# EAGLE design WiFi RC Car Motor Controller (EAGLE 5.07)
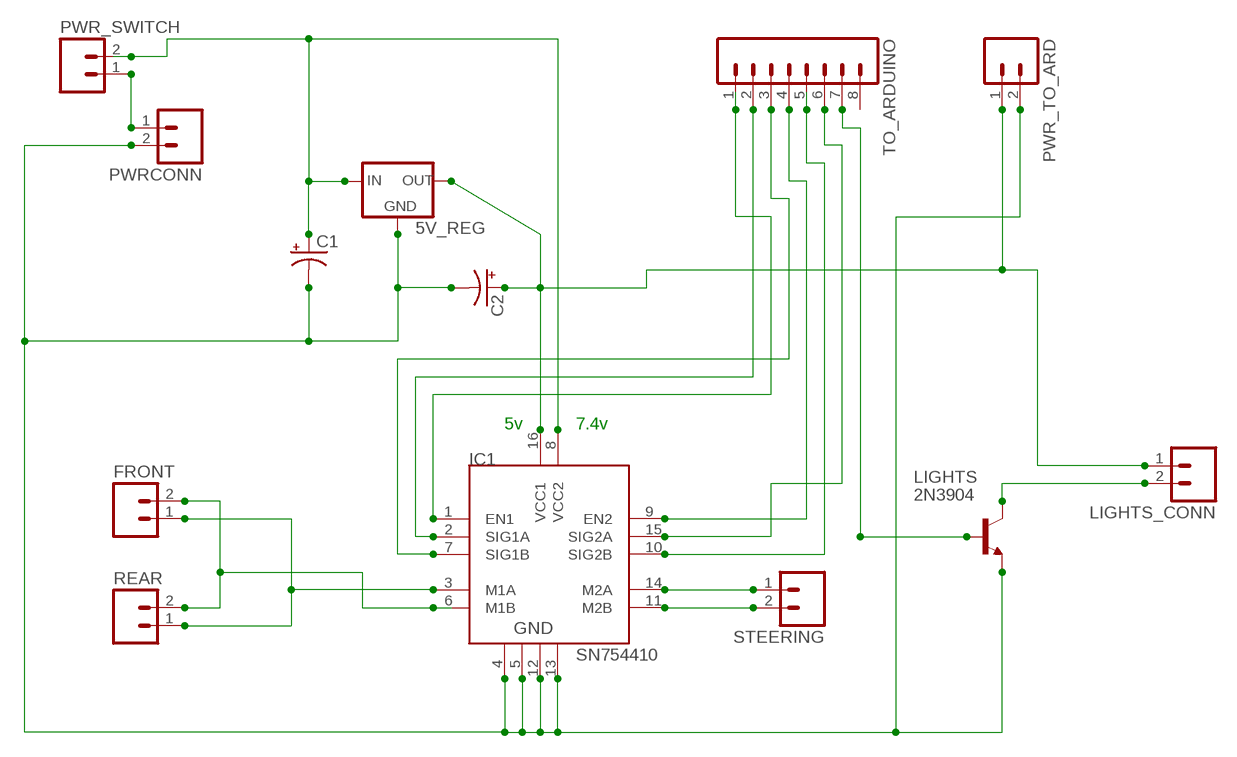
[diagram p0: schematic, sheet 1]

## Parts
5V_REG  V_REG_78XXSIDE  [78XXL]
C1  CAP_POLPTH2  [CPOL-RADIAL-10UF-25V]
C2  CAP_POLPTH2  [CPOL-RADIAL-10UF-25V]
FRONT  M023.5MM  [SCREWTERMINAL-3.5MM-2]
IC1  SN754410  [DIP16]
LIGHTS  2N3904  [TO92]
LIGHTS_CONN  M023.5MM  [SCREWTERMINAL-3.5MM-2]
PWR_SWITCH  M023.5MM  [SCREWTERMINAL-3.5MM-2]
PWR_TO_ARD  M023.5MM  [SCREWTERMINAL-3.5MM-2]
PWRCONN  M023.5MM  [SCREWTERMINAL-3.5MM-2]
REAR  M023.5MM  [SCREWTERMINAL-3.5MM-2]
STEERING  M023.5MM  [SCREWTERMINAL-3.5MM-2]
TO_ARDUINO  M08LONGPADS  [1X08_LONGPADS]

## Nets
N$1: FRONT.1 IC1.3(M1A) REAR.1
N$2: 5V_REG.GND C1.2(-) C2.2(-) IC1.4 IC1.5 IC1.12 IC1.13 LIGHTS.3(E) PWR_TO_ARD.2 PWRCONN.2
N$3: FRONT.2 IC1.6(M1B) REAR.2
N$4: IC1.14(M2A) STEERING.1
N$5: IC1.11(M2B) STEERING.2
N$6: PWR_SWITCH.1 PWRCONN.1
N$7: 5V_REG.IN C1.1(+) IC1.8(VCC2) PWR_SWITCH.2
N$8: 5V_REG.OUT C2.1(+) IC1.16(VCC1) LIGHTS_CONN.1 PWR_TO_ARD.1
N$9: IC1.1(EN1) TO_ARDUINO.1
N$10: IC1.2(SIG1A) TO_ARDUINO.2
N$11: IC1.7(SIG1B) TO_ARDUINO.3
N$12: LIGHTS.2(B) TO_ARDUINO.7
N$13: IC1.9(EN2) TO_ARDUINO.4
N$14: IC1.15(SIG2A) TO_ARDUINO.6
N$15: IC1.10(SIG2B) TO_ARDUINO.5
N$18: LIGHTS.1(C) LIGHTS_CONN.2
Unconnected: TO_ARDUINO.8

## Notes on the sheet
- 5v | 7.4v

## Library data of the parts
5V_REG = SparkFun:V_REG_78XX: Voltage Regulator Standard 7805 5V regulator. IGO (Input Ground Output). Spark Fun Electronics SKU : COM-00107
C1 C2 = SparkFun:CAP_POL: Capacitor Polarized
FRONT LIGHTS_CONN PWR_SWITCH PWR_TO_ARD PWRCONN REAR STEERING = SparkFun:M02: Header 2
IC1 = HBridge:SN754410: Quadruple half-H driver
LIGHTS = transistor:2N3904: NPN TRANSISTOR
TO_ARDUINO = SparkFun:M08: Header 8 Standard 8-pin 0.1" header. Use with straight break away headers (SKU : PRT-00116), right angle break away headers (PRT-00553), swiss pins (PRT-00743), machine pins (PRT-00117), and female headers (PRT-00115).

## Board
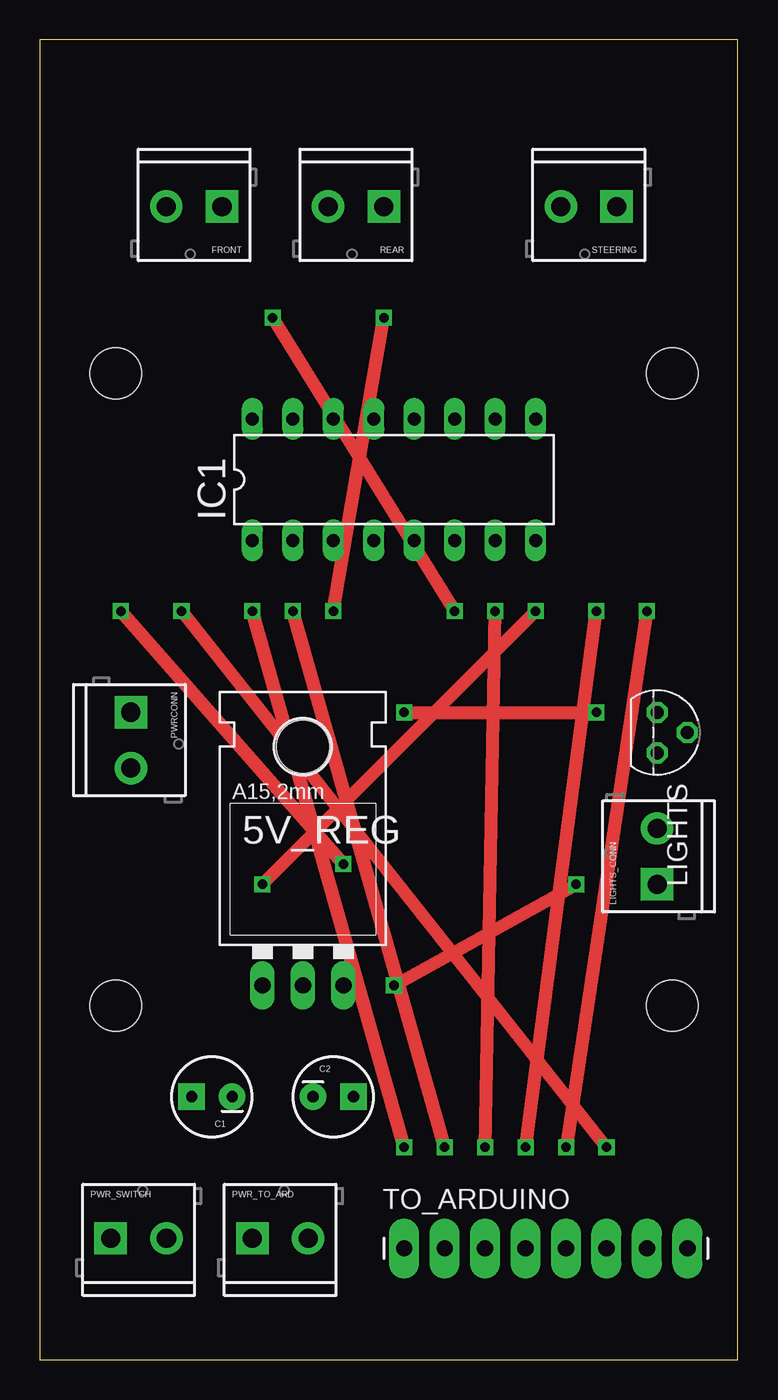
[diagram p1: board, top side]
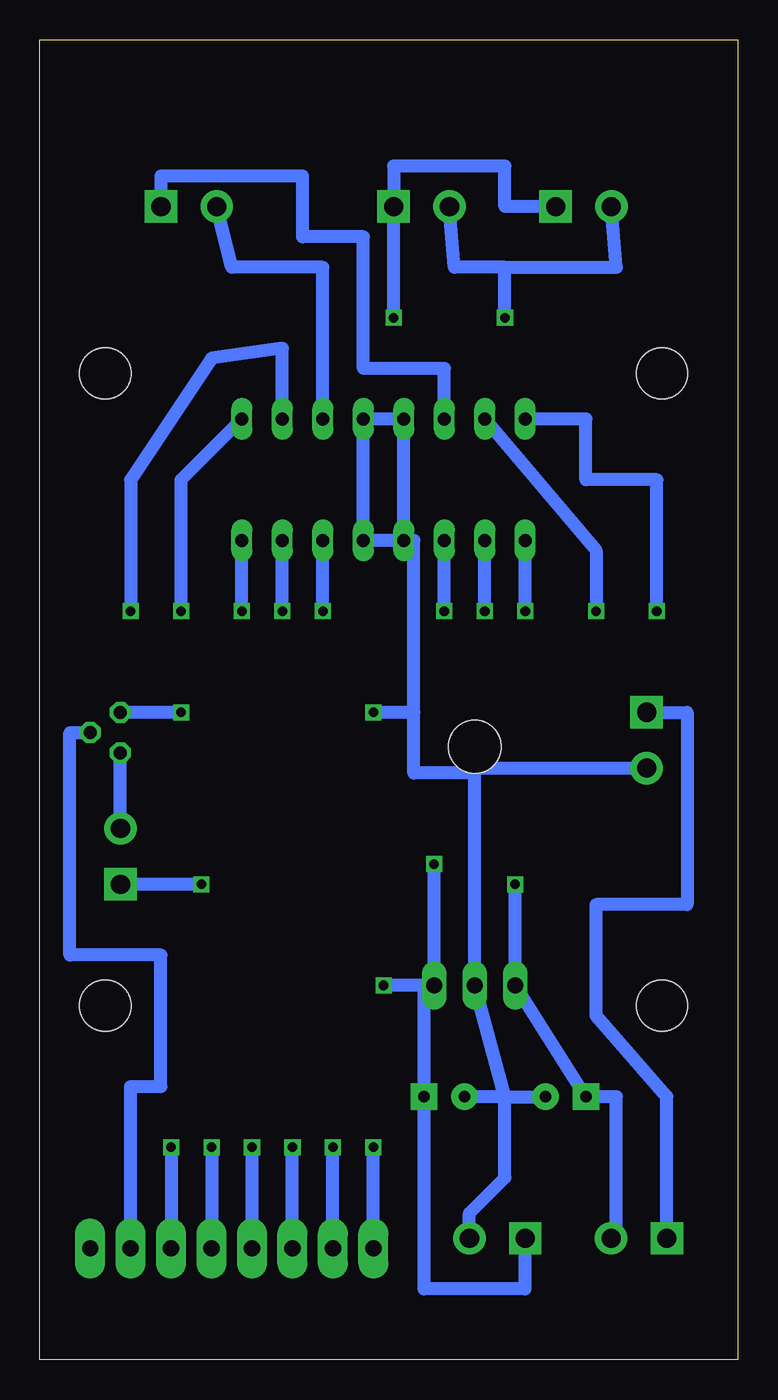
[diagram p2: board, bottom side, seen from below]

Size 43.8 x 82.86 mm. Coordinates in mm from the lower left corner, seen from the top.
Outline: 0,0 43.8,0 43.8,82.86 0,82.86 0,0
Copper layers (1*16): Top 0.035mm / dielectric 1.5mm / Bottom 0.035mm
Design rules "default": minimum track width 10mil, minimum drill 24mil, track to track 8mil, track to pad 8mil, pad to pad 8mil, via to via 8mil, smd to smd 8mil, copper to edge 40mil, drill to drill 8mil, minimum pad ring 10mil, minimum via ring 8mil, stop-mask expansion 4mil, vias tented up to drill 0mil, thermal gap 10mil
Holes 3.2 mm at 4.76,61.91 39.69,61.91 4.76,22.23 39.69,22.23

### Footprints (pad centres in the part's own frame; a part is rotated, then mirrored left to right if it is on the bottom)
78XXL = drill 1.016 long: GND 0,-3.81; IN -2.54,-3.81; OUT 2.54,-3.81 | hole 3.302: 0,11.176
CPOL-RADIAL-10UF-25V = drill 0.7 pad 1.651 square: 1 1.27,0 | drill 0.7 pad 1.651 round: 2 -1.27,0
SCREWTERMINAL-3.5MM-2 = drill 1.2 pad 2.032 square: 1 0,0 | drill 1.2 pad 2.032 round: 2 3.5,0
DIP16 = drill 0.813 long: 1 -10.16,-3.81; 2 -7.62,-3.81; 3 -5.08,-3.81; 4 -2.54,-3.81; 5 0,-3.81; 6 2.54,-3.81; 7 5.08,-3.81; 8 7.62,-3.81; 9 7.62,3.81; 10 5.08,3.81; 11 2.54,3.81; 12 0,3.81; 13 -2.54,3.81; 14 -5.08,3.81; 15 -7.62,3.81; 16 -10.16,3.81
TO92 = drill 0.813 octagon: 1 1.27,0; 2 0,1.905; 3 -1.27,0
1X08_LONGPADS = drill 1.016 pad 1.88 long: 1 0,0; 2 2.54,0; 3 5.08,0; 4 7.62,0; 5 10.16,0; 6 12.7,0; 7 15.24,0; 8 17.78,0

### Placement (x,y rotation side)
5V_REG  16.51,27.3 0 top
C1  10.79,16.51 180 top
C2  18.41,16.51 0 top
FRONT  11.43,72.39 180 top
IC1  23.5,55.24 0 top
LIGHTS  38.73,39.37 270 top
LIGHTS_CONN  38.73,29.84 90 top
PWR_SWITCH  4.45,7.62 0 top
PWR_TO_ARD  13.34,7.62 0 top
PWRCONN  5.71,40.64 270 top
REAR  21.59,72.39 180 top
STEERING  36.2,72.39 180 top
TO_ARDUINO  22.86,6.99 0 top

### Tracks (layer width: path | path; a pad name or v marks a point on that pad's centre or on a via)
N$1  (via drill 0.6)
  Top 0.813: v18.41,46.99 v21.59,65.41
  Bottom 0.813: v18.41,46.99 IC1.3 | v21.59,65.41 REAR.1 21.59,74.93 14.61,74.93 14.61,72.39 FRONT.1
N$2  (via drill 0.6)  (1 unrouted)
  Top 0.813: v22.86,40.64 34.92,40.64
  Bottom 0.813: 14.61,16.51 C1.2 | 14.61,16.51 14.61,11.43 16.84,9.2 PWR_TO_ARD.2 | 14.61,16.51 14.65,16.67 | 14.65,16.67 5V_REG.GND 16.51,36.83 | C2.2 14.65,16.51 14.65,16.67 | PWRCONN.2 16.51,37.14 16.51,36.83 | IC1.4 20.32,51.44 20.32,40.64 | 20.32,40.64 20.32,36.83 16.51,36.83 | IC1.4 IC1.5 IC1.12 IC1.13 IC1.4 | 34.92,40.64 LIGHTS.3 | 20.32,40.64 v22.86,40.64
N$3  (via drill 0.6)
  Top 0.813: v26.04,46.99 v14.61,65.41
  Bottom 0.813: FRONT.2 7.62,68.58 14.61,68.58 | 14.61,68.58 17.78,68.58 REAR.2 | v26.04,46.99 IC1.6 | v14.61,65.41 14.61,68.58
N$4
  Bottom 0.813: IC1.14 18.41,62.23 23.5,62.23 23.5,70.48 27.3,70.48 27.3,74.3 36.2,74.3 STEERING.1
N$5
  Bottom 0.813: IC1.11 26.04,68.58 31.75,68.58 STEERING.2
N$6
  Bottom 0.813: PWR_SWITCH.1 4.45,16.51 8.89,21.59 8.89,28.57 3.17,28.57 3.17,40.64 PWRCONN.1
N$7  (via drill 0.6)
  Top 0.813: v13.97,29.84 v31.11,46.99
  Bottom 0.813: PWR_SWITCH.2 7.62,7.62 7.62,16.51 C1.1 5V_REG.IN v13.97,29.84 | v31.11,46.99 IC1.8
N$8  (via drill 0.6)
  Top 0.813: v22.23,23.5 v33.66,29.84 | v19.05,31.11 v5.08,46.99
  Bottom 0.813: PWR_TO_ARD.1 13.34,4.45 19.68,4.45 C2.1 19.68,23.5 | 19.68,23.5 5V_REG.OUT v19.05,31.11 | v33.66,29.84 LIGHTS_CONN.1 | 19.68,23.5 v22.23,23.5 | v5.08,46.99 5.08,55.24 9.53,55.24 9.53,59.05 IC1.16
N$9  (via drill 0.6)
  Top 0.813: v22.86,13.34 v13.34,46.99
  Bottom 0.813: TO_ARDUINO.1 v22.86,13.34 | v13.34,46.99 IC1.1
N$10  (via drill 0.6)
  Top 0.813: v25.4,13.34 v15.88,46.99
  Bottom 0.813: TO_ARDUINO.2 v25.4,13.34 | v15.88,46.99 IC1.2
N$11  (via drill 0.6)
  Top 0.813: v27.94,13.34 v28.57,46.99
  Bottom 0.813: TO_ARDUINO.3 v27.94,13.34 | v28.57,46.99 IC1.7
N$12
  Bottom 0.813: TO_ARDUINO.7 38.1,17.14 36.2,17.14 36.2,25.4 41.91,25.4 41.91,39.37 LIGHTS.2
N$13  (via drill 0.6)
  Top 0.813: v30.48,13.34 v34.92,46.99
  Bottom 0.813: TO_ARDUINO.4 v30.48,13.34 | v34.92,46.99 34.92,55.24 IC1.9
N$14  (via drill 0.6)
  Top 0.813: v8.89,46.99 v35.56,13.34
  Bottom 0.813: IC1.15 8.89,50.8 v8.89,46.99 | v35.56,13.34 TO_ARDUINO.6 35.56,6.35
N$15  (via drill 0.6)
  Top 0.813: v38.1,46.99 v33.02,13.34
  Bottom 0.813: IC1.10 28.57,63.5 33.02,62.87 38.1,55.24 v38.1,46.99 | v33.02,13.34 TO_ARDUINO.5
N$16  (via drill 0.6)
  other vias: 22.23,23.5
N$17  (via drill 0.6)
  other vias: 33.66,29.84
N$18
  Bottom 0.813: LIGHTS_CONN.2 LIGHTS.1
N$19  (via drill 0.6)
  other vias: 34.92,40.64
N$20  (via drill 0.6)
  other vias: 22.86,40.64
N$21  (via drill 0.6)
  other vias: 19.05,31.11
N$22  (via drill 0.6)
  other vias: 5.08,46.99
N$23  (via drill 0.6)
  other vias: 13.34,46.99
N$24  (via drill 0.6)
  other vias: 15.88,46.99
N$25  (via drill 0.6)
  other vias: 18.41,46.99
N$26  (via drill 0.6)
  other vias: 35.56,13.34
N$27  (via drill 0.6)
  other vias: 33.02,13.34
N$28  (via drill 0.6)
  other vias: 30.48,13.34
N$29  (via drill 0.6)
  other vias: 27.94,13.34
N$30  (via drill 0.6)
  other vias: 25.4,13.34
N$31  (via drill 0.6)
  other vias: 22.86,13.34
N$32  (via drill 0.6)
  other vias: 28.57,46.99
N$33  (via drill 0.6)
  other vias: 31.11,46.99
N$34  (via drill 0.6)
  other vias: 26.04,46.99
N$35  (via drill 0.6)
  other vias: 14.61,65.41
N$36  (via drill 0.6)
  other vias: 8.89,46.99
N$37  (via drill 0.6)
  other vias: 38.1,46.99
